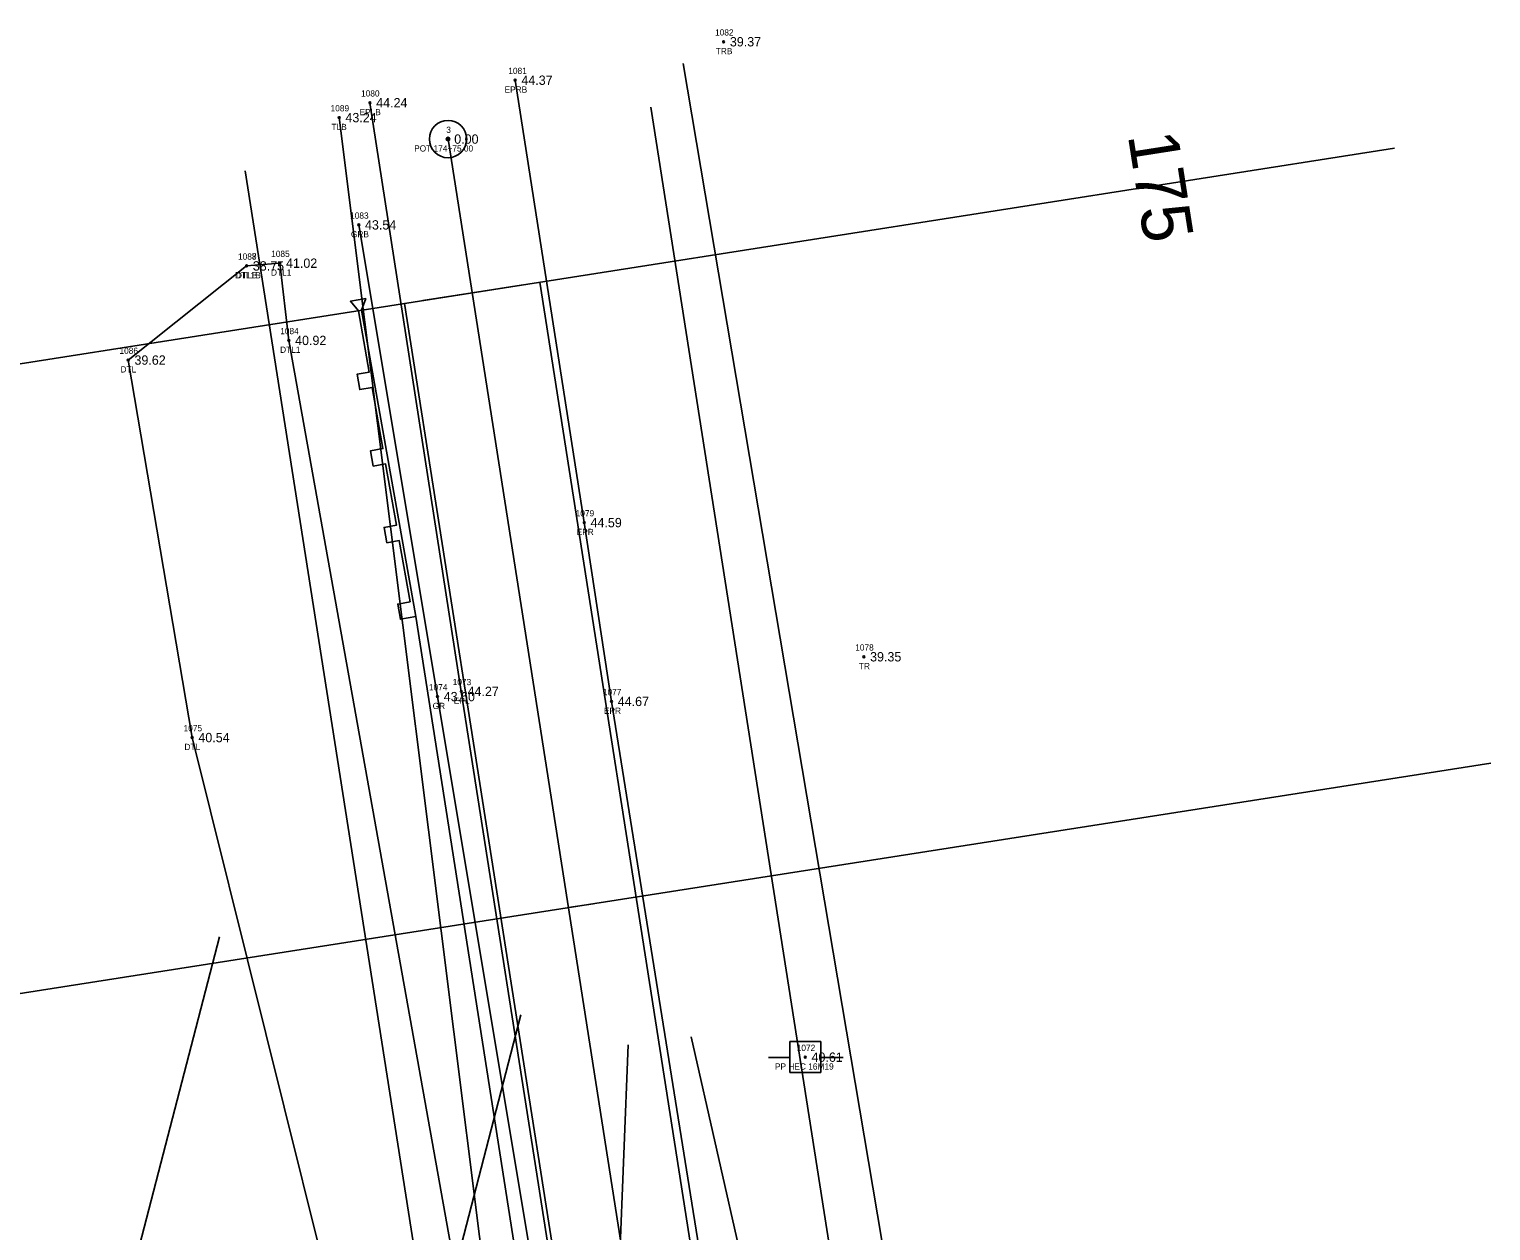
# Model space of a CAD drawing. Extents: x 2619568 to 2620316, y 784340 to 785138.
# Drawn here: x 2619722.2 to 2619957.1, y 784945.3 to 785138.4 of the extents above; entities that cross this region are included whole.
import ezdxf

# ---------------------------------------------------------------- set-up
doc = ezdxf.new("R2010")
doc.units = 0
for name, color, linetype in [('RD_EX_GuardRail', 7, 'Continuous'), ('RD_EX_GuardRail_txCode', 7, 'Continuous'), ('RD_EX_H2O', 7, 'Continuous'), ('RD_EX_H2O_txCode', 7, 'Continuous'), ('RD_EX_Road', 7, 'Continuous'), ('RD_EX_Road_txCode', 7, 'Continuous'), ('RD_EX_RW', 7, 'Continuous'), ('RD_EX_TX_GuardRail_ELEV', 7, 'Continuous'), ('RD_EX_TX_H2O_ELEV', 7, 'Continuous'), ('RD_EX_TX_Road_ELEV', 7, 'Continuous'), ('RD_EX_TX_VEG_ELEV', 7, 'Continuous'), ('RD_EX_UT', 7, 'Continuous'), ('RD_EX_UT_txCode', 7, 'Continuous'), ('RD_EX_VEG', 7, 'Continuous'), ('RD_EX_VEG_txCode', 7, 'Continuous'), ('RD_HC_Cl', 7, 'Continuous'), ('RD_HC_Data', 7, 'Continuous'), ('RD_HC_Data_Tic', 7, 'Continuous'), ('RD_HC_Survey_ELEV', 7, 'Continuous'), ('RD_HC_TX_Sta50', 7, 'Continuous'), ('RD_HC_txCode', 7, 'Continuous'), ('RD_PD_Final_TrvlWay', 7, 'Continuous'), ('RD_PD_GR', 7, 'Continuous'), ('RD_PD_PatLn1', 7, 'Continuous'), ('RD_PD_PatLn2', 7, 'Continuous'), ('RD_SMD_Locator', 7, 'Continuous')]:
    doc.layers.add(name, color=color, linetype=linetype)

msp = doc.modelspace()

# ---------------------------------------------------------------- linework, layer by layer
at = {"layer": 'RD_EX_GuardRail'}
msp.add_lwpolyline([(2619867.12, 784523.3), (2619850.86, 784633.15), (2619824.72, 784807.66), (2619818.35, 784847.92), (2619803.75, 784935.38), (2619787.81, 785031.17), (2619775.16, 785106.97)], dxfattribs=at)
at = {"layer": 'RD_EX_H2O'}
for points in [[(2619772.64, 784911.68), (2619772.05, 784929.46), (2619748.39, 785024.59), (2619738.12, 785085.25), (2619757.14, 785100.38)], [(2619791.73, 784933.03), (2619763.93, 785088.41), (2619762.47, 785100.82), (2619757.14, 785100.38)]]:
    msp.add_lwpolyline(points, dxfattribs=at)
at = {"layer": 'RD_EX_Road'}
for p, q in [((2619811.4, 785059.13), (2619800.29, 785130.22)), ((2619791.64, 785032.01), (2619776.96, 785126.6)), ((2619815.78, 785030.4), (2619811.4, 785059.13)), ((2619806.71, 784935.63), (2619791.64, 785032.01)), ((2619830.54, 784938.02), (2619815.78, 785030.4))]:
    msp.add_line(p, q, dxfattribs=at)
at = {"layer": 'RD_EX_RW'}
for p, q in [((2619822.1, 785125.87), (2619915.04, 784533.11)), ((2619756.9, 785115.64), (2619849.84, 784522.89))]:
    msp.add_line(p, q, dxfattribs=at)
at = {"layer": 'RD_EX_UT'}
for p, q in [((2619849.4, 784975.74), (2619844.4, 784975.74)), ((2619844.4, 784975.74), (2619844.4, 784970.74)), ((2619849.4, 784970.74), (2619849.4, 784975.74)), ((2619840.97, 784973.17), (2619844.44, 784973.17)), ((2619849.33, 784973.17), (2619852.97, 784973.17)), ((2619844.4, 784970.74), (2619849.4, 784970.74))]:
    msp.add_line(p, q, dxfattribs=at)
at = {"layer": 'RD_EX_VEG'}
for points in [[(2619930.82, 784519.47), (2619827.3, 785132.88)], [(2619857.01, 784520.73), (2619804.77, 784862.84), (2619772.02, 785124.21)]]:
    msp.add_lwpolyline(points, dxfattribs=at)
at = {"layer": 'RD_HC_Cl'}
msp.add_line((2619789.5, 785120.76), (2619882.44, 784528), dxfattribs=at)
at = {"layer": 'RD_HC_Data'}
for radius in [3, 0.282]:
    msp.add_circle((2619789.5, 785120.76), radius, dxfattribs=at)
at = {"layer": 'RD_HC_Data_Tic'}
for p, q in [((2619793.37, 785096.06), (2619785.47, 785094.82)), ((2619793.37, 785096.06), (2619801.28, 785097.3)), ((2619808.86, 784997.26), (2619812.81, 784997.88))]:
    msp.add_line(p, q, dxfattribs=at)
at = {"layer": 'RD_PD_Final_TrvlWay'}
for p, q in [((2619804.24, 785097.76), (2619881.69, 784603.8)), ((2619782.51, 785094.35), (2619859.95, 784600.39))]:
    msp.add_line(p, q, dxfattribs=at)
at = {"layer": 'RD_PD_GR'}
msp.add_line((2619851.12, 784617.98), (2619784.32, 785044.03), dxfattribs=at)
msp.add_lwpolyline([(2619775.59, 785093.26), (2619784.32, 785044.03), (2619781.86, 785043.59), (2619781.42, 785046.05), (2619783.4, 785046.4), (2619781.66, 785056.25), (2619779.68, 785055.9), (2619779.24, 785058.36), (2619781.22, 785058.71), (2619779.47, 785068.56), (2619777.5, 785068.21), (2619777.06, 785070.67), (2619779.04, 785071.02), (2619777.29, 785080.86), (2619775.31, 785080.51), (2619774.88, 785082.98), (2619776.85, 785083.33), (2619775.11, 785093.17), (2619773.82, 785094.7), (2619776.27, 785095.14)], close=True, dxfattribs=at)
at = {"layer": 'RD_PD_PatLn1'}
for p, q in [((2619941.56, 785119.29), (2619645.18, 785072.82)), ((2619957.05, 785020.5), (2619660.67, 784974.03))]:
    msp.add_line(p, q, dxfattribs=at)
at = {"layer": 'RD_PD_PatLn2'}
for p, q in [((2619752.78, 784992.56), (2619677.57, 784702.14)), ((2619801.18, 784980.03), (2619725.97, 784689.61)), ((2619828.58, 784976.51), (2619894.93, 784683.94)), ((2619818.47, 784975.2), (2619806.39, 784675.45))]:
    msp.add_line(p, q, dxfattribs=at)
at = {"layer": 'RD_SMD_Locator'}
for centre in [(2619833.79, 785136.4), (2619800.29, 785130.22), (2619776.96, 785126.6), (2619772.02, 785124.21), (2619789.5, 785120.76), (2619775.16, 785106.97), (2619757.14, 785100.38), (2619757.14, 785100.38), (2619762.47, 785100.82), (2619763.93, 785088.41), (2619738.12, 785085.25), (2619811.4, 785059.13), (2619856.32, 785037.57), (2619791.64, 785032.01), (2619787.81, 785031.17), (2619815.78, 785030.4), (2619748.39, 785024.59), (2619846.91, 784973.23)]:
    msp.add_circle(centre, 0.15, dxfattribs=at)

# ---------------------------------------------------------------- texts
at = {"layer": 'RD_EX_GuardRail_txCode'}
for s, p in [('1083', (2619773.77, 785107.97)), ('GRB', (2619773.9, 785104.97)), ('1074', (2619786.43, 785032.17)), ('GR', (2619787.03, 785029.17))]:
    msp.add_text(s, height=1, dxfattribs=at).set_placement(p)
at = {"layer": 'RD_EX_H2O_txCode'}
for s, p in [('1087', (2619755.76, 785101.38)), ('1088', (2619755.76, 785101.38)), ('1085', (2619761.08, 785101.82)), ('DTL1B', (2619755.26, 785098.38)), ('DTLB', (2619755.43, 785098.38)), ('DTL1', (2619761.06, 785098.82)), ('1084', (2619762.54, 785089.41)), ('1086', (2619736.71, 785086.25)), ('DTL1', (2619762.52, 785086.41)), ('DTL', (2619736.88, 785083.25)), ('1075', (2619747.01, 785025.59)), ('DTL', (2619747.15, 785022.59))]:
    msp.add_text(s, height=1, dxfattribs=at).set_placement(p)
at = {"layer": 'RD_EX_Road_txCode'}
for s, p in [('1081', (2619799.19, 785131.22)), ('1080', (2619775.53, 785127.6)), ('EPRB', (2619798.59, 785128.22)), ('EPLB', (2619775.28, 785124.6)), ('1079', (2619810.01, 785060.13)), ('EPR', (2619810.17, 785057.13)), ('1073', (2619790.25, 785033.01)), ('1077', (2619814.39, 785031.4)), ('EPL', (2619790.43, 785030.01)), ('EPR', (2619814.55, 785028.4))]:
    msp.add_text(s, height=1, dxfattribs=at).set_placement(p)
at = {"layer": 'RD_EX_TX_GuardRail_ELEV'}
for s, p in [('43.54', (2619776.16, 785106.22)), ('43.60', (2619788.81, 785030.42))]:
    msp.add_text(s, height=1.5, dxfattribs=at).set_placement(p)
at = {"layer": 'RD_EX_TX_H2O_ELEV'}
for s, p in [('38.75', (2619758.14, 785099.63)), ('38.75', (2619758.14, 785099.63)), ('41.02', (2619763.47, 785100.07)), ('40.92', (2619764.93, 785087.66)), ('39.62', (2619739.12, 785084.5)), ('40.54', (2619749.39, 785023.84))]:
    msp.add_text(s, height=1.5, dxfattribs=at).set_placement(p)
at = {"layer": 'RD_EX_TX_Road_ELEV'}
for s, p in [('44.37', (2619801.29, 785129.47)), ('44.24', (2619777.96, 785125.85)), ('44.59', (2619812.4, 785058.38)), ('44.27', (2619792.64, 785031.26)), ('44.67', (2619816.78, 785029.65))]:
    msp.add_text(s, height=1.5, dxfattribs=at).set_placement(p)
at = {"layer": 'RD_EX_TX_VEG_ELEV'}
for s, p in [('39.37', (2619834.79, 785135.65)), ('43.24', (2619773.02, 785123.46)), ('39.35', (2619857.32, 785036.82))]:
    msp.add_text(s, height=1.5, dxfattribs=at).set_placement(p)
at = {"layer": 'RD_EX_UT_txCode'}
for s, p in [('1072', (2619845.53, 784974.23)), ('PP HEC 16M19', (2619842.03, 784971.23))]:
    msp.add_text(s, height=1, dxfattribs=at).set_placement(p)
at = {"layer": 'RD_EX_VEG_txCode'}
for s, p in [('1082', (2619832.41, 785137.4)), ('TRB', (2619832.52, 785134.4)), ('1089', (2619770.63, 785125.21)), ('TLB', (2619770.77, 785122.21)), ('1078', (2619854.93, 785038.57)), ('TR', (2619855.52, 785035.57))]:
    msp.add_text(s, height=1, dxfattribs=at).set_placement(p)
at = {"layer": 'RD_HC_Survey_ELEV'}
for s, p in [('0.00', (2619790.5, 785120.01)), ('40.61', (2619847.91, 784972.48))]:
    msp.add_text(s, height=1.5, dxfattribs=at).set_placement(p)
at = {"layer": 'RD_HC_TX_Sta50'}
msp.add_text('175', height=8, rotation=278.9109, dxfattribs=at).set_placement((2619898.72, 785121.38))
at = {"layer": 'RD_HC_txCode'}
for s, p in [('3', (2619789.22, 785121.76)), ('POT 174+75.00', (2619784.06, 785118.76))]:
    msp.add_text(s, height=1, dxfattribs=at).set_placement(p)

doc.saveas('drawing.dxf')
